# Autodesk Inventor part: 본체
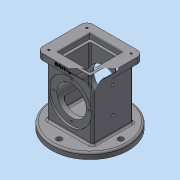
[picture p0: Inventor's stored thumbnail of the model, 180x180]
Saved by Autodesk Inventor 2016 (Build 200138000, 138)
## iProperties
Created: 2018-10
Part Number: 본체
Material: 일반
Document SubType Name: Modeling
Designer: Administrator
Density: 1 g/cm^3
Appearance: 기본값
Author: Administrator
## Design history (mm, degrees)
sketch "스케치1"
  geometry: C1 r 62.5 at (0, 0); 1 further point
  constraints: 1 centre point, 1 coincident
  dimensions: "d0" = 125 diameter of C1
extrude "돌출1" new body sketch "스케치1" distance "d1" = 10; taper "d2" = 0 deg
sketch "스케치2"
  geometry: L1 (37, -33)-(-37, -33); L2 (-37, -33)-(-37, 33); L3 (-37, 33)-(37, 33); L4 (37, 33)-(37, -33); L5 (37, -33)-(-37, 33); L6 (-37, -33)-(37, 33); 1 further point
  constraints: 12 end point, 2 midpoint, 2 parallel, 1 horizontal, 1 perpendicular
  dimensions: "d3" = 66 distance of L1.end L2.end; "d4" = 74 distance of L2.end L3.end
extrude "돌출2" join sketch "스케치2" distance "d5" = 88; taper "d6" = 0 deg
sketch "스케치3"
  geometry: L1 (-46, 41)-(46, 41); L2 (46, 41)-(46, -41); L3 (46, -41)-(-46, -41); L4 (-46, -41)-(-46, 41); L5 (-46, 41)-(46, -41); L6 (46, 41)-(-46, -41); 1 further point
  constraints: 12 end point, 2 midpoint, 2 parallel, 1 horizontal, 1 perpendicular
  dimensions: "d8" = 82 distance of L1.end L2.end; "d9" = 92 distance of L1.start L1.end
extrude "돌출3" join sketch "스케치3" distance "d10" = 10; taper "d11" = 0 deg
sketch "스케치4"
  geometry: L1 (26, -26)-(-26, -26); L2 (-26, -26)-(-26, 26); L3 (-26, 26)-(26, 26); L4 (26, 26)-(26, -26); L5 (26, -26)-(-26, 26); L6 (-26, -26)-(26, 26); L7 (46, 41)-(-46, 41) reference; L8 (-46, 41)-(-46, -41) reference; 1 further point
  constraints: 12 end point, 2 midpoint, 2 parallel, 1 horizontal, 1 perpendicular
  dimensions: "d14" = 52 distance of L1.end L2.end; "d15" = 52 distance of L2.end L3.end
extrude "돌출4" cut sketch "스케치4" distance "d16" = 8; taper "d17" = 0 deg
sketch "스케치5"
  geometry: L1 (22, -22)-(-22, -22); L2 (-22, -22)-(-22, 22); L3 (-22, 22)-(22, 22); L4 (22, 22)-(22, -22); L5 (22, -22)-(-22, 22); L6 (-22, -22)-(22, 22); 1 further point
  constraints: 12 end point, 2 midpoint, 2 parallel, 1 horizontal, 1 perpendicular
  dimensions: "d18" = 44 distance of L2.end L3.end; "d19" = 44 distance of L1.end L2.end
extrude "돌출5" cut sketch "스케치5" distance "d20" = 74; taper "d21" = 0 deg
sketch "스케치6"
  geometry: L1 (0, 0)-(34.923, 0); L2 (18, 0)-(18, -24.826); L3 (18, -24.826)-(0, -28); L4 (0, -28)-(0, 0); L5 (0, 62.5)-(0, -62.5) reference; L6 (0, 0)-(18, 0)
  constraints: 10 end point, 2 collinear, 1 horizontal, 1 point on line, 1 vertical
  dimensions: "d22" = 80 deg angle of L4 L3; "d23" = 18 distance between parallel lines of L4 L2; "d24" = 28 distance of L3.end L1.start
revolve "회전1" sketch "스케치6" stored, may be unused: angle "d25" = 90 deg
sketch "스케치7"
  geometry: L1 (-25.5, -10)-(99.5, -10) reference; C1 r 35 at (37, 44); 2 further points
  constraints: 1 centre point, 1 midpoint, 1 vertical alignment
  dimensions: "d26" = 70 diameter of C1; "d27" = 54 distance from line of L1 C1.centre
extrude "돌출6" cut sketch "스케치7" distance "d28" = 3; taper "d29" = 0 deg
sketch "스케치8"
  geometry: C1 r 24 at (0, 0); C2 r 35 at (0, 0) reference; 1 further point
  constraints: 1 centre point, 1 concentric
  dimensions: "d30" = 48 diameter of C1
extrude "돌출7" cut sketch "스케치8" stored distance "d31" = 3; taper "d32" = 0 deg
sketch "스케치9"
  geometry: L1 (0, 10)-(92, 10) reference; L2 (0, 0)-(0, 10) reference; 2 further points
  constraints: 1 other
  dimensions: "d33" = 4 distance from line of L1 point (46, 6); "d34" = 46 distance from line of L2 point (46, 6)
feature "엠보싱1" sketch "스케치9" dims "d35" = 0.5, "d36" = 0
sketch "스케치10" dims "d37" = 58
  geometry: C1 r 24 at (0, 0) reference; 3 further points
  constraints: 2 vertical alignment, 3 other
hole "구멍1" sketch "스케치10" at (0, 29) diameter "d38" = 3.242; stored, may be unused: countersink angle "d42" = 90 deg, drill point angle "d44" = 118 deg; dims "d39" = 4, "d40" = 4, "d41" = 2, "d43" = 6
sketch "스케치11"
  geometry: L1 (36, 31)-(-36, 31); L2 (-36, 31)-(-36, -31); L3 (-36, -31)-(36, -31); L4 (36, -31)-(36, 31); L5 (36, 31)-(-36, -31); L6 (-36, 31)-(36, -31); 5 further points
  constraints: 12 end point, 4 coincident, 2 midpoint, 2 parallel, 1 horizontal, 1 perpendicular
  dimensions: "d48" = 72 distance of L1.start L1.end; "d49" = 62 distance of L1.end L2.end
hole "구멍2" sketch "스케치11" at (-36, -31), (36, -31), (36, 31), (-36, 31) diameter "d50" = 3.242; stored, may be unused: countersink angle "d54" = 90 deg, drill point angle "d56" = 118 deg; dims "d51" = 4, "d52" = 4, "d53" = 2, "d55" = 6
sketch "스케치12" dims "d57" = 100
  geometry: 3 further points
  constraints: 2 horizontal alignment, 1 coincident, 2 other
hole "구멍3" sketch "스케치12" at (-50, 0) diameter "d58" = 9; stored, may be unused: countersink angle "d62" = 90 deg, drill point angle "d64" = 118 deg; dims "d59" = 4, "d60" = 4, "d61" = 2, "d63" = 10
sketch "스케치13"
  geometry: L1 (-29.5, -10)-(95.5, -10) reference; 4 further points
  constraints: 2 vertical alignment, 1 midpoint
  dimensions: "d68" = 37 distance from line of L1 point (33, 27); "d69" = 43 distance of point (33, 70) point (33, 27)
hole "구멍4" sketch "스케치13" at (33, 70), (33, 27) diameter "d70" = 4.134; stored, may be unused: countersink angle "d74" = 90 deg, drill point angle "d76" = 118 deg; dims "d71" = 20, "d72" = 4, "d73" = 2, "d75" = 20
fillet "모깎기1" dims "d77" = 10
fillet "모깎기2" dims "d78" = 3
chamfer "모따기1" distance "d79" = 1; stored, may be unused: second distance "d80" = 2, angle "d81" = 45 deg
chamfer "모따기2" distance "d82" = 1; stored, may be unused: second distance "d83" = 2, angle "d84" = 45 deg
chamfer "모따기3" distance "d85" = 1; stored, may be unused: second distance "d86" = 2, angle "d87" = 45 deg
chamfer "모따기4" distance "d88" = 1; stored, may be unused: second distance "d89" = 2, angle "d90" = 45 deg
fillet "모깎기3" dims "d91" = 3
sketch "스케치14"
  geometry: L1 (36, -114.79)-(126.336, -114.79); L2 (126.336, -114.79)-(126.336, 34.666); L3 (126.336, 34.666)-(36, 34.666); L4 (36, 34.666)-(36, -114.79); 1 further point
  constraints: 8 end point, 2 parallel, 1 horizontal, 1 perpendicular
extrude "돌출8" cut sketch "스케치14" stored distance "d92" = 0; taper "d93" = 0 deg
node "솔리드1"
mirror "대칭1"
pattern_circular "원형 패턴1" dims angle "d46" = 360 deg
mirror "대칭2"
pattern_circular "원형 패턴2" dims angle "d66" = 360 deg
